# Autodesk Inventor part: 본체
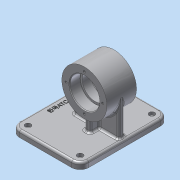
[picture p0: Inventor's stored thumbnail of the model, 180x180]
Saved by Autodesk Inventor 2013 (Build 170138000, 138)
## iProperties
Created: 2019-09
Part Number: 본체
Material: 알루미늄 6061
Document SubType Name: Modeling
Designer: Administrator
Density: 2.71 g/cm^3
Mass: 556.668 g
Surface Area: 495.884 cm^2
Volume: 205.413 cm^3
Author: Administrator
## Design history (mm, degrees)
sketch "스케치1"
  geometry: C1 r 32 at (0, 0); 1 further point
  constraints: 1 centre point, 1 coincident
  dimensions: "d0" = 64 diameter of C1
extrude "돌출1" new body sketch "스케치1" stored distance "d1" = 42; taper "d2" = 0 deg
sketch "스케치2"
  geometry: L1 (-62, -50)-(36, -50); L2 (36, -50)-(36, -59); L3 (36, -59)-(-62, -59); L4 (-62, -59)-(-62, -50); 1 further point
  constraints: 8 end point, 2 parallel, 1 horizontal, 1 perpendicular
  dimensions: "d3" = 59 distance from line of L3 point (0, 0); "d4" = 9 distance of L1.end L2.end; "d5" = 36 distance from line of L2 point (0, 0); "d6" = 98 distance of L2.end L3.end
extrude "돌출2" join sketch "스케치2" stored distance "d7" = 126; taper "d8" = 0 deg
sketch "스케치3"
  geometry: C1 r 32 at (0, 0) reference; C2 r 21 at (0, 0)
  constraints: 1 centre point, 1 coincident
  dimensions: "d9" = 42 diameter of C2
extrude "돌출3" cut sketch "스케치3" distance "d10" = 15; taper "d11" = 0 deg
hole "구멍1" diameter "d14" = 36; stored, may be unused: countersink angle "d18" = 90 deg, drill point angle "d20" = 118 deg; dims "d12" = 10, "d13" = 10, "d15" = 6, "d16" = 42, "d17" = 15, "d19" = 8
chamfer "모따기1" distance "d21" = 1; stored, may be unused: second distance "d22" = 2, angle "d23" = 45 deg
fillet "모깎기1" dims "d24" = 0.3
sketch "스케치4"
  geometry: C1 r 32 at (0, 0) reference; 1 further point
  constraints: 1 vertical alignment
  dimensions: "d25" = 26 distance of C1.centre point (0, 26)
hole "구멍2" sketch "스케치4" at (0, 26) diameter "d26" = 3.242; stored, may be unused: countersink angle "d30" = 90 deg, drill point angle "d32" = 118 deg; dims "d27" = 8, "d28" = 42, "d29" = 15, "d31" = 10
sketch "스케치5"
  geometry: L1 (30, 59)-(94, 59); L2 (94, 59)-(94, 67); L3 (94, 67)-(30, 67); L4 (30, 67)-(30, 59); L5 (58, 46)-(66, 46); L6 (66, 46)-(66, 80); L7 (66, 80)-(58, 80); L8 (58, 80)-(58, 46); 5 further points
  constraints: 16 end point, 4 midpoint, 4 parallel, 2 horizontal, 2 horizontal alignment, 2 perpendicular, 2 vertical alignment
  dimensions: "d36" = 8 distance of L3.end L1.start; "d38" = 64 distance of L2.end L3.end; "d44" = 8 distance of L5.start L5.end; "d45" = 34 distance of L7.end L5.start
extrude "돌출4" join sketch "스케치5" stored distance "d39" = 15; taper "d40" = 0 deg
fillet "모깎기2" dims "d46" = 12
sketch "스케치7"
  geometry: A1 r 12 centre (74, -12) between (86, -12) and (74, 0) reference; A2 r 12 centre (0, -12) between (0, 0) and (-12, -12) reference; A3 r 12 centre (0, -114) between (-12, -114) and (0, -126) reference; A4 r 12 centre (74, -114) between (74, -126) and (86, -114) reference; 5 further points
  constraints: 4 coincident
hole "구멍3" sketch "스케치7" at (0, -12), (74, -12), (0, -114), (74, -114) diameter "d47" = 4.5; stored, may be unused: countersink angle "d51" = 90 deg, drill point angle "d53" = 118 deg; dims "d48" = 8, "d49" = 8, "d50" = 4.4, "d52" = 10
fillet "모깎기3" dims "d54" = 3
fillet "모깎기4" dims "d55" = 3
sketch "스케치8"
  geometry: L1 (74, 3)-(0, 3) reference; L2 (-12, -9)-(-12, -111) reference; 2 further points
  constraints: 1 other
  dimensions: "d56" = 63 distance from line of L1 point (-2, -60); "d57" = 10 distance from line of point (-2, -60) L2
feature "엠보싱1" sketch "스케치8" dims "d58" = 0.5, "d59" = 0
node "솔리드1"
pattern_circular "원형 패턴1" dims angle "d34" = 360 deg
mirror "대칭1"
